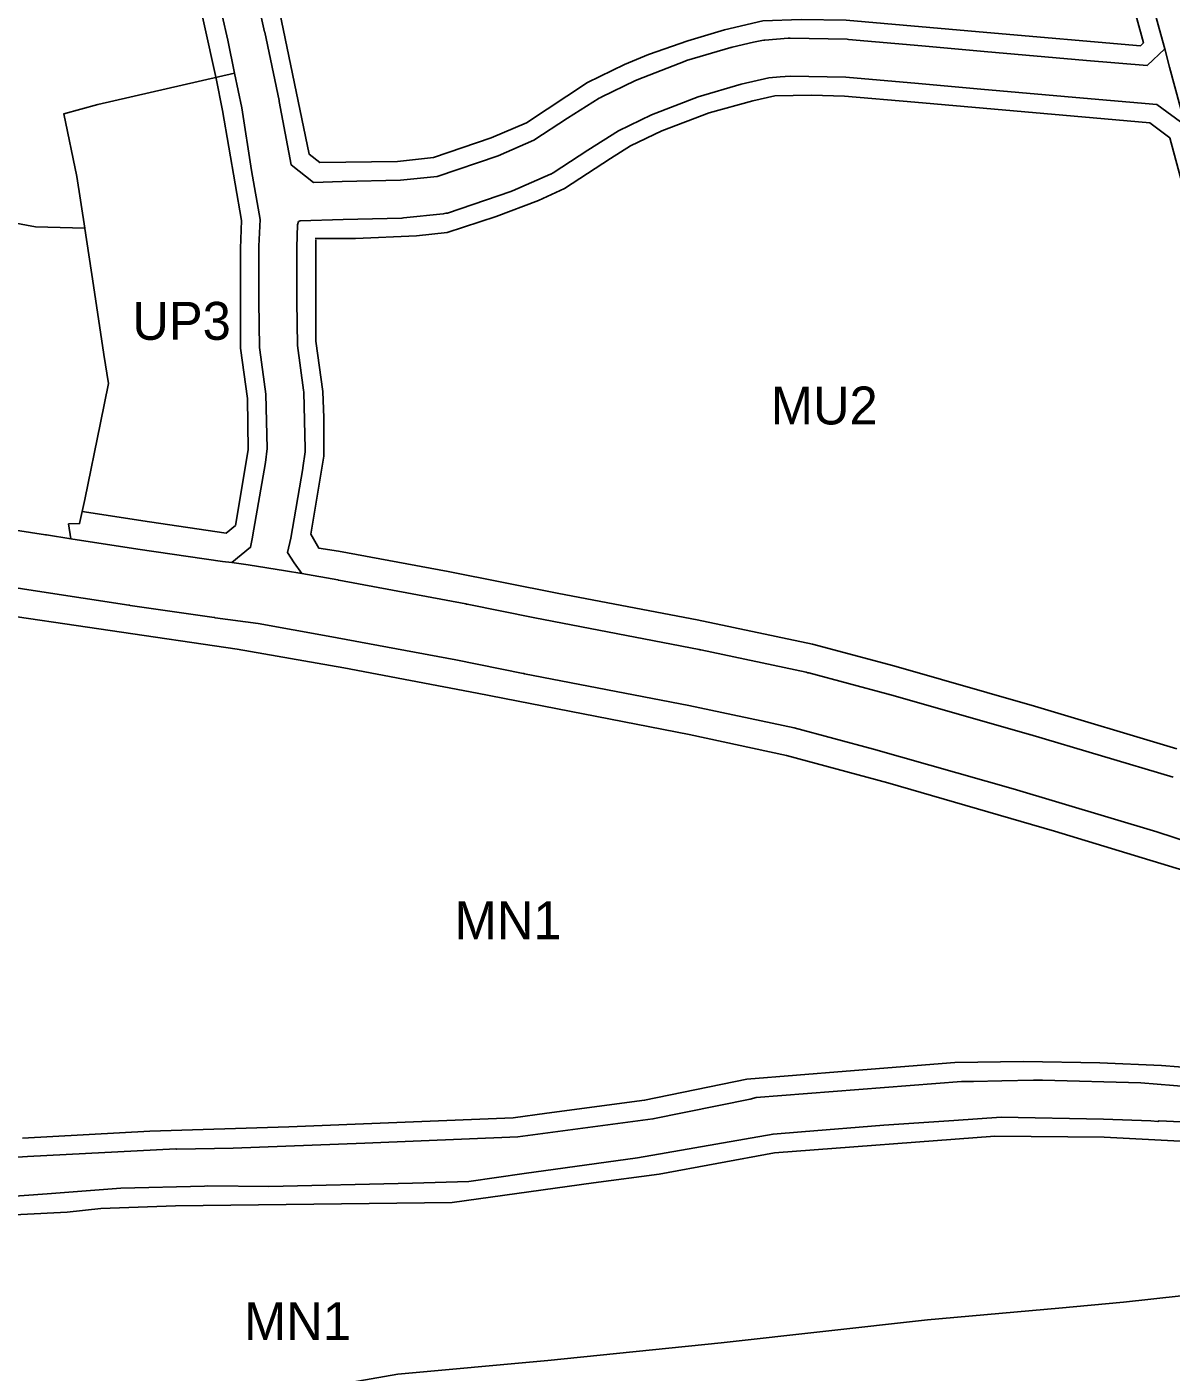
# Model space of a CAD drawing. Extents: x -284239 to -281592, y 34477 to 37267.
# Drawn here: x -282543.7 to -282241.7, y 34820.9 to 35175.9 of the extents above; entities that cross this region are included whole.
import ezdxf

# ---------------------------------------------------------------- set-up
doc = ezdxf.new("R2010")
doc.units = 0
for name, color, linetype in [('linie_rozgraniczajace', 7, 'Continuous'), ('linie_zabudowy_nieprzekraczalne', 7, 'Continuous'), ('oznaczenia_przeznaczen', 7, 'Continuous')]:
    doc.layers.add(name, color=color, linetype=linetype)

msp = doc.modelspace()

# ---------------------------------------------------------------- linework, layer by layer
at = {"layer": 'linie_rozgraniczajace'}
for points in [[(-282546.171, 35312.91), (-282537.013, 35297.146), (-282530.123, 35284.351), (-282525.422, 35275.176), (-282515.543, 35255.372), (-282510.592, 35245.61), (-282506.662, 35236.471), (-282503.721, 35226.637), (-282497.121, 35200.281), (-282493.649, 35185.49), (-282490.701, 35172.369), (-282488.867, 35163.617), (-282525.01, 35155.389), (-282533.9, 35152.937), (-282530.528, 35136.381), (-282528.402, 35122.716), (-282541.458, 35123.137), (-282556.202, 35125.799)], [(-282253.402, 35206.78), (-282244.814, 35175.442), (-282243.406, 35170.048), (-282248.028, 35165.722), (-282264.006, 35167.035), (-282291.019, 35169.361), (-282307.473, 35170.911), (-282307.507, 35170.913), (-282326.851, 35172.586), (-282327.172, 35172.601), (-282342.284, 35172.901), (-282342.544, 35172.852), (-282342.766, 35172.888), (-282348.974, 35172.41), (-282349.196, 35172.357), (-282349.698, 35172.301), (-282351.911, 35171.798), (-282357.577, 35170.51), (-282357.786, 35170.443), (-282357.888, 35170.429), (-282369.587, 35166.967), (-282369.941, 35166.841), (-282369.972, 35166.836), (-282382.626, 35161.941), (-282382.82, 35161.814), (-282383.023, 35161.768), (-282392.155, 35157.291), (-282392.25, 35157.223), (-282392.615, 35157.034), (-282400.972, 35151.782), (-282400.998, 35151.761), (-282401.034, 35151.742), (-282409.888, 35145.993), (-282419.343, 35141.828), (-282435.372, 35136.409), (-282445.121, 35135.412), (-282460.457, 35135.057), (-282468.061, 35134.841), (-282473.905, 35139.444), (-282477.103, 35156.201), (-282477.135, 35156.314), (-282477.149, 35156.453), (-282480.921, 35174.455), (-282480.933, 35174.493), (-282480.937, 35174.526), (-282483.897, 35187.705)], [(-282213.365, 35044.823), (-282214.504, 35058.766), (-282216.807, 35069.514), (-282220.363, 35085.26), (-282228.359, 35115.489), (-282234.602, 35138.644), (-282237.884, 35149.865), (-282239.35, 35154.875), (-282242.151, 35165.239), (-282243.406, 35170.048), (-282244.814, 35175.442), (-282253.402, 35206.78)], [(-282483.897, 35187.705), (-282480.937, 35174.526), (-282480.933, 35174.493), (-282480.921, 35174.455), (-282477.149, 35156.453), (-282477.135, 35156.314), (-282477.103, 35156.201), (-282473.905, 35139.444), (-282468.061, 35134.841), (-282460.457, 35135.057), (-282445.121, 35135.412), (-282435.372, 35136.409), (-282419.343, 35141.828), (-282409.888, 35145.993), (-282401.034, 35151.742), (-282400.998, 35151.761), (-282400.972, 35151.782), (-282392.615, 35157.034), (-282392.25, 35157.223), (-282392.155, 35157.291), (-282383.023, 35161.768), (-282382.82, 35161.814), (-282382.626, 35161.941), (-282369.972, 35166.836), (-282369.941, 35166.841), (-282369.587, 35166.967), (-282357.888, 35170.429), (-282357.786, 35170.443), (-282357.577, 35170.51), (-282351.911, 35171.798), (-282349.698, 35172.301), (-282349.196, 35172.357), (-282348.974, 35172.41), (-282342.766, 35172.888), (-282342.544, 35172.852), (-282342.284, 35172.901), (-282327.172, 35172.601), (-282326.851, 35172.586), (-282307.507, 35170.913), (-282307.473, 35170.911), (-282291.019, 35169.361), (-282264.006, 35167.035), (-282248.028, 35165.722), (-282243.406, 35170.048), (-282242.151, 35165.239), (-282239.35, 35154.875)], [(-282471.558, 35124.737), (-282471.983, 35124.513), (-282472.247, 35123.664), (-282472.458, 35117.734), (-282472.458, 35103.535), (-282472.284, 35091.763), (-282470.656, 35080.011), (-282470.62, 35079.492), (-282470.609, 35079.444), (-282470.251, 35064.522), (-282470.262, 35064.464), (-282470.25, 35064.402), (-282470.29, 35063.773), (-282470.827, 35059.535), (-282470.849, 35059.452), (-282470.862, 35059.303), (-282474.073, 35040.928), (-282474.896, 35037.177), (-282473.108, 35034.49), (-282471.101, 35031.6), (-282475.459, 35032.371), (-282485.289, 35033.914), (-282489.583, 35034.503), (-282484.634, 35038.585), (-282484.17, 35041.234), (-282484.165, 35041.262), (-282484.155, 35041.298), (-282484.151, 35041.351), (-282480.733, 35060.909), (-282480.258, 35064.658), (-282480.6, 35078.919), (-282482.232, 35090.695), (-282482.272, 35091.274), (-282482.279, 35091.307), (-282482.458, 35103.424), (-282482.451, 35103.461), (-282482.458, 35103.498), (-282482.458, 35117.823), (-282482.44, 35117.917), (-282482.455, 35118.002), (-282482.138, 35125.049), (-282484.376, 35138.018), (-282486.963, 35154.527), (-282488.867, 35163.617), (-282490.701, 35172.369), (-282493.649, 35185.49)], [(-282241.154, 34977.859), (-282279.01, 34989.12), (-282279.098, 34989.133), (-282279.335, 34989.216), (-282316.052, 34999.682), (-282316.159, 34999.697), (-282316.406, 34999.781), (-282337.35, 35005.411), (-282337.599, 35005.443), (-282338.005, 35005.57), (-282365.836, 35011.497), (-282366.035, 35011.518), (-282366.235, 35011.578), (-282409.632, 35019.917), (-282427.465, 35023.529), (-282427.652, 35023.547), (-282427.824, 35023.599), (-282461.347, 35029.874), (-282461.525, 35029.89), (-282461.669, 35029.932), (-282471.101, 35031.6), (-282473.108, 35034.49), (-282474.896, 35037.177), (-282474.073, 35040.928), (-282470.862, 35059.303), (-282470.849, 35059.452), (-282470.827, 35059.535), (-282470.29, 35063.773), (-282470.25, 35064.402), (-282470.262, 35064.464), (-282470.251, 35064.522), (-282470.609, 35079.444), (-282470.62, 35079.492), (-282470.656, 35080.011), (-282472.284, 35091.763), (-282472.458, 35103.535), (-282472.458, 35117.734), (-282472.247, 35123.664), (-282471.983, 35124.513), (-282471.558, 35124.737), (-282460.199, 35125.061), (-282444.693, 35125.419), (-282444.665, 35125.425), (-282444.3, 35125.444), (-282433.795, 35126.518), (-282433.139, 35126.684), (-282432.702, 35126.756), (-282415.929, 35132.426), (-282415.75, 35132.537), (-282415.515, 35132.587), (-282405.487, 35137.004), (-282405.424, 35137.047), (-282404.78, 35137.386), (-282395.619, 35143.335), (-282387.517, 35148.428), (-282378.816, 35152.693), (-282366.554, 35157.435), (-282355.204, 35160.794), (-282347.84, 35162.468), (-282344.893, 35162.695), (-282342.24, 35162.899), (-282327.546, 35162.608), (-282308.392, 35160.953), (-282291.937, 35159.403), (-282291.901, 35159.401), (-282264.852, 35157.071), (-282245.473, 35155.402), (-282237.884, 35149.865)], [(-282237.884, 35149.865), (-282245.473, 35155.402), (-282264.852, 35157.071), (-282291.901, 35159.401), (-282291.937, 35159.403), (-282308.392, 35160.953), (-282327.546, 35162.608), (-282342.24, 35162.899), (-282344.893, 35162.695), (-282347.84, 35162.468), (-282355.204, 35160.794), (-282366.554, 35157.435), (-282378.816, 35152.693), (-282387.517, 35148.428), (-282395.619, 35143.335), (-282404.78, 35137.386), (-282405.424, 35137.047), (-282405.487, 35137.004), (-282415.515, 35132.587), (-282415.75, 35132.537), (-282415.929, 35132.426), (-282432.702, 35126.756), (-282433.139, 35126.684), (-282433.795, 35126.518), (-282444.3, 35125.444), (-282444.665, 35125.425), (-282444.693, 35125.419), (-282460.199, 35125.061), (-282471.558, 35124.737)], [(-282556.202, 35125.799), (-282541.458, 35123.137), (-282528.402, 35122.716), (-282528.362, 35122.714), (-282526.081, 35107.675), (-282523.419, 35089.466), (-282522.194, 35081.735), (-282524.306, 35071.427), (-282528.404, 35051.191), (-282529.798, 35044.812), (-282532.671, 35044.728), (-282532.093, 35040.824), (-282538.521, 35041.82), (-282538.676, 35041.832), (-282538.772, 35041.859), (-282551.853, 35043.871)], [(-282551.853, 35043.871), (-282538.772, 35041.859), (-282538.676, 35041.832), (-282538.521, 35041.82), (-282532.093, 35040.824), (-282514.396, 35038.082), (-282492.083, 35034.846), (-282489.583, 35034.503), (-282485.289, 35033.914), (-282475.459, 35032.371), (-282471.101, 35031.6), (-282461.669, 35029.932), (-282461.525, 35029.89), (-282461.347, 35029.874), (-282427.824, 35023.599), (-282427.652, 35023.547), (-282427.465, 35023.529), (-282409.632, 35019.917), (-282366.235, 35011.578), (-282366.035, 35011.518), (-282365.836, 35011.497), (-282338.005, 35005.57), (-282337.599, 35005.443), (-282337.35, 35005.411), (-282316.406, 34999.781), (-282316.159, 34999.697), (-282316.052, 34999.682), (-282279.335, 34989.216), (-282279.098, 34989.133), (-282279.01, 34989.12), (-282241.154, 34977.859)], [(-282553.966, 35029.016), (-282540.909, 35027.007), (-282516.752, 35023.264), (-282516.548, 35023.248), (-282516.432, 35023.216), (-282494.298, 35020.006), (-282494.098, 35019.992), (-282493.993, 35019.964), (-282482.68, 35018.411), (-282464.184, 35015.14), (-282430.511, 35008.837), (-282412.696, 35005.229), (-282412.531, 35005.212), (-282412.375, 35005.166), (-282369.016, 34996.834), (-282341.212, 34990.912), (-282320.277, 34985.284), (-282283.42, 34974.778), (-282245.462, 34963.487), (-282236.047, 34960.422)], [(-282236.047, 34960.422), (-282245.462, 34963.487), (-282283.42, 34974.778), (-282320.277, 34985.284), (-282341.212, 34990.912), (-282369.016, 34996.834), (-282412.375, 35005.166), (-282412.531, 35005.212), (-282412.696, 35005.229), (-282430.511, 35008.837), (-282464.184, 35015.14), (-282482.68, 35018.411), (-282493.993, 35019.964), (-282494.098, 35019.992), (-282494.298, 35020.006), (-282516.432, 35023.216), (-282516.548, 35023.248), (-282516.752, 35023.264), (-282540.909, 35027.007), (-282553.966, 35029.016)], [(-282189.34, 34892.357), (-282249.679, 34897.225), (-282275.668, 34897.982), (-282278.023, 34897.937), (-282286.38, 34897.778), (-282293.878, 34897.635), (-282295.537, 34897.603), (-282297.058, 34897.574), (-282351.189, 34893.377), (-282352.824, 34892.955), (-282378.481, 34887.726), (-282414.107, 34882.986), (-282454.473, 34881.352), (-282489.282, 34880.044), (-282504.135, 34879.695), (-282504.352, 34879.825), (-282543.51, 34877.775), (-282565.868, 34876.32)], [(-282565.868, 34876.32), (-282543.51, 34877.775), (-282504.352, 34879.825), (-282504.135, 34879.695), (-282489.282, 34880.044), (-282454.473, 34881.352), (-282414.107, 34882.986), (-282378.481, 34887.726), (-282352.824, 34892.955), (-282351.189, 34893.377), (-282297.058, 34897.574), (-282295.537, 34897.603), (-282293.878, 34897.635), (-282286.38, 34897.778), (-282278.023, 34897.937), (-282275.668, 34897.982), (-282249.679, 34897.225), (-282189.34, 34892.357)], [(-282550.522, 34867.059), (-282538.351, 34867.985), (-282518.904, 34869.44), (-282496.811, 34869.969), (-282495.902, 34870.068), (-282479.804, 34869.912), (-282441.889, 34870.729), (-282427.018, 34871.22), (-282412.473, 34873.344), (-282382.567, 34877.43), (-282346.747, 34883.702), (-282339.257, 34884.315), (-282317.539, 34886.044), (-282299.088, 34887.294), (-282286.595, 34888.159), (-282259.591, 34887.678), (-282247.099, 34887.198), (-282245.185, 34887.042), (-282244.885, 34887.223), (-282235.321, 34886.807)], [(-282235.321, 34886.807), (-282244.885, 34887.223), (-282245.185, 34887.042), (-282247.099, 34887.198), (-282259.591, 34887.678), (-282286.595, 34888.159), (-282299.088, 34887.294), (-282317.539, 34886.044), (-282339.257, 34884.315), (-282346.747, 34883.702)], [(-282346.747, 34883.702), (-282382.567, 34877.43), (-282412.473, 34873.344), (-282427.018, 34871.22), (-282441.889, 34870.729), (-282479.804, 34869.912), (-282495.902, 34870.068), (-282496.811, 34869.969), (-282518.904, 34869.44), (-282538.351, 34867.985), (-282550.522, 34867.059)], [(-282551.698, 34795.154), (-282520.433, 34806.265), (-282503.638, 34810.657), (-282492.832, 34812.392), (-282475.474, 34815.179), (-282445.759, 34820.347), (-282406.225, 34823.964), (-282360.49, 34828.615), (-282305.97, 34834.688), (-282271.337, 34837.805), (-282254.292, 34839.339), (-282223.802, 34842.698), (-282209.622, 34844.001), (-282198.128, 34845.058), (-282194.495, 34845.392), (-282166.182, 34847.995), (-282145.769, 34849.286), (-282122.255, 34849.028), (-282101.068, 34846.832), (-282079.627, 34843.782), (-282040.771, 34833.185)], [(-282223.802, 34842.698), (-282254.292, 34839.339), (-282271.337, 34837.805), (-282305.97, 34834.688), (-282360.49, 34828.615), (-282406.225, 34823.964), (-282445.759, 34820.347)]]:
    msp.add_lwpolyline(points, dxfattribs=at)
msp.add_lwpolyline([(-282533.9, 35152.937), (-282525.01, 35155.389), (-282488.867, 35163.617), (-282486.963, 35154.527), (-282484.376, 35138.018), (-282482.138, 35125.049), (-282482.455, 35118.002), (-282482.44, 35117.917), (-282482.458, 35117.823), (-282482.458, 35103.498), (-282482.451, 35103.461), (-282482.458, 35103.424), (-282482.279, 35091.307), (-282482.272, 35091.274), (-282482.232, 35090.695), (-282480.6, 35078.919), (-282480.258, 35064.658), (-282480.733, 35060.909), (-282484.151, 35041.351), (-282484.155, 35041.298), (-282484.165, 35041.262), (-282484.17, 35041.234), (-282484.634, 35038.585), (-282489.583, 35034.503), (-282492.083, 35034.846), (-282514.396, 35038.082), (-282532.093, 35040.824), (-282532.671, 35044.728), (-282529.798, 35044.812), (-282528.404, 35051.191), (-282524.306, 35071.427), (-282522.194, 35081.735), (-282523.419, 35089.466), (-282526.081, 35107.675), (-282528.362, 35122.714), (-282528.402, 35122.716), (-282530.528, 35136.381)], close=True, dxfattribs=at)
at = {"layer": 'linie_zabudowy_nieprzekraczalne'}
for points in [[(-282529.086, 35048.012), (-282511.358, 35045.234), (-282491.118, 35042.323), (-282488.604, 35044.308), (-282485.297, 35064.284), (-282485.429, 35077.844), (-282487.281, 35091.073), (-282487.281, 35117.399), (-282487.017, 35124.741), (-282492.044, 35153.846), (-282493.764, 35162.246), (-282500.246, 35191.681), (-282507.522, 35221.711), (-282511.623, 35235.205), (-282514.533, 35242.283), (-282532.393, 35278.002), (-282539.801, 35291.628), (-282550.385, 35310.148)], [(-282484.91, 35214.141), (-282477.492, 35182.09), (-282469.157, 35142.27), (-282466.379, 35140.087), (-282445.874, 35140.352), (-282436.349, 35141.41), (-282421.135, 35146.57), (-282411.875, 35150.538), (-282395.735, 35161.188), (-282385.946, 35165.95), (-282379.596, 35168.596), (-282369.277, 35172.168), (-282359.62, 35175.078), (-282349.433, 35177.46), (-282339.379, 35177.857), (-282327.473, 35177.658), (-282290.299, 35174.351), (-282249.817, 35170.911), (-282249.024, 35171.705), (-282255.77, 35196.444), (-282260.665, 35215.163), (-282266.618, 35238.975), (-282269.926, 35255.115), (-282273.772, 35278.699)], [(-282230.767, 35104.765), (-282242.012, 35146.57), (-282247.304, 35150.538), (-282262.253, 35151.861), (-282309.349, 35156.028), (-282327.87, 35157.616), (-282336.601, 35157.88), (-282346.258, 35157.682), (-282352.079, 35156.359), (-282363.588, 35153.184), (-282376.156, 35148.422), (-282384.358, 35144.453), (-282389.65, 35141.146), (-282401.821, 35133.208), (-282408.7, 35130.033), (-282419.812, 35125.866), (-282432.777, 35121.632), (-282440.847, 35120.706), (-282456.986, 35120.045), (-282467.57, 35120.045)], [(-282467.438, 35119.648), (-282467.438, 35092.925), (-282465.585, 35079.696), (-282465.321, 35072.684), (-282465.321, 35062.564), (-282468.76, 35042.059), (-282466.644, 35038.355), (-282461.484, 35037.561), (-282432.512, 35032.137), (-282403.276, 35026.382), (-282366.763, 35019.371), (-282336.336, 35012.955), (-282314.905, 35007.266), (-282277.731, 34996.617), (-282240.16, 34985.372)], [(-282238.308, 34953.291), (-282272.439, 34963.676), (-282316.492, 34976.376), (-282343.215, 34983.586), (-282368.88, 34989.142), (-282424.84, 35000.056), (-282460.029, 35006.737), (-282488.207, 35011.632), (-282555.279, 35021.554)], [(-282544.833, 34882.603), (-282511.231, 34884.455), (-282474.586, 34885.646), (-282415.319, 34888.027), (-282406.456, 34889.218), (-282380.659, 34892.658), (-282353.66, 34898.211), (-282327.473, 34900.308), (-282298.765, 34902.623), (-282280.641, 34902.888), (-282260.533, 34902.491), (-282244.261, 34901.829), (-282235.265, 34901.102)], [(-282215.294, 34843.842), (-282203.388, 34874.534), (-282203.917, 34876.253), (-282214.632, 34878.767), (-282226.142, 34880.619), (-282235.931, 34881.677), (-282259.347, 34882.868), (-282288.187, 34883.133), (-282346.395, 34878.767), (-282376.826, 34873.108), (-282394.153, 34870.829), (-282431.455, 34865.663), (-282504.484, 34864.744), (-282524.196, 34864.082), (-282533.059, 34863.156), (-282590.738, 34860.246), (-282607.804, 34856.145), (-282640.745, 34852.308), (-282666.012, 34849.266)]]:
    msp.add_lwpolyline(points, dxfattribs=at)

# ---------------------------------------------------------------- texts
at = {"layer": 'oznaczenia_przeznaczen'}
for s, p in [('UP3', (-282515.879, 35093.301)), ('MU2', (-282347.378, 35070.972)), ('MN1', (-282430.807, 34935.133)), ('MN1', (-282486.382, 34829.36))]:
    msp.add_text(s, height=10, dxfattribs=at).set_placement(p)

doc.saveas('drawing.dxf')
